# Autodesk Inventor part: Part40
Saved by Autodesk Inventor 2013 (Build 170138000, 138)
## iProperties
Created: 2012-07
Part Number: Part40
Material: Acetal Resin, Black
Document SubType Name: Modeling
Designer: Paul
Density: 1 g/cm^3
Author: Paul
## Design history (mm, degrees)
node "User Library-Arduino Mega.SAT1"
body "Solid1"
node "Base1"
